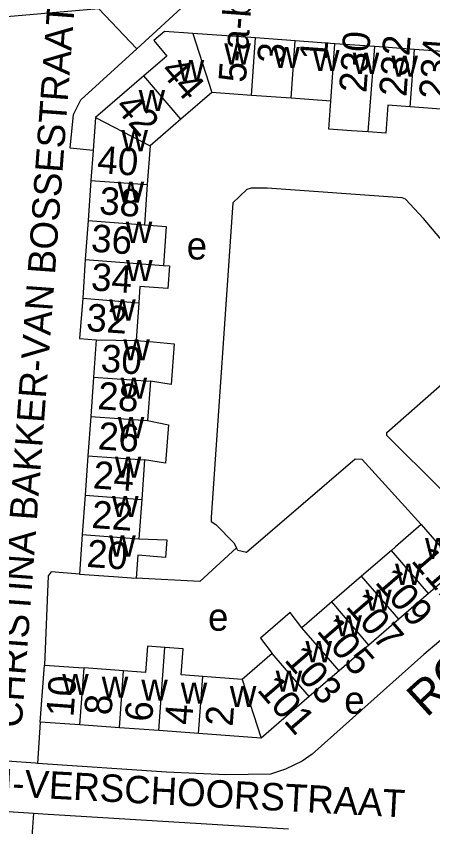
# Model space of a CAD drawing. Extents: x 159902 to 161769, y 383692 to 384875.
# Drawn here: x 160524 to 160584.8, y 384027.3 to 384145.4 of the extents above; entities that cross this region are included whole.
import ezdxf

# ---------------------------------------------------------------- set-up
doc = ezdxf.new("R2010")
doc.units = 0
for name, color, linetype in [('BLT_Basislijn', 7, 'Continuous'), ('BLT_Bebouwing', 7, 'Continuous'), ('BLT_Centroide', 7, 'Continuous'), ('BLT_Huisnummer', 7, 'Continuous'), ('BLT_Huisnummer_ tussenligend', 7, 'Continuous'), ('BLT_Huisnummer_reeks', 7, 'Continuous'), ('BLT_Onderverdeling_panden', 7, 'Continuous'), ('BLT_Straatnaam', 7, 'Continuous'), ('BLT_Straatnaam_verkleind', 7, 'Continuous')]:
    doc.layers.add(name, color=color, linetype=linetype)

msp = doc.modelspace()

# ---------------------------------------------------------------- linework, layer by layer
at = {"layer": 'BLT_Basislijn'}
for p, q in [((160527.54, 384042.53), (160527.14, 384036.5)), ((160526.52, 384029.24), (160526.04, 384022.51))]:
    msp.add_line(p, q, dxfattribs=at)
for points in [[(160541.6, 384140.66), (160549.25, 384147.65), (160552.82, 384148.62), (160554.65, 384148.85)], [(160509.95, 384136.94), (160519.25, 384145.08), (160536.04, 384146.55), (160541.6, 384140.66)], [(160535.25, 384125.85), (160531.91, 384126.2), (160532.4, 384131.11), (160533.47, 384133.24), (160541.6, 384140.66)], [(160585.91, 384076.54), (160578.09, 384084.32), (160578.09, 384084.74), (160597.85, 384102.11), (160597.75, 384111.32), (160594.69, 384114.92), (160593.48, 384115.14), (160588.64, 384111.22), (160587.65, 384110.93), (160583.44, 384115.94), (160580.8, 384118.74), (160580.32, 384118.93), (160560.65, 384120.34), (160558.3, 384120.35), (160557.69, 384120.18), (160555.62, 384118.2), (160552.47, 384072.33), (160552.47, 384071.77), (160553.15, 384071.33), (160555.77, 384068.67), (160556.14, 384067.93)], [(160583.12, 384071.32), (160574.47, 384080.78), (160573.47, 384080.87), (160557.63, 384067.24), (160556.34, 384067.55), (160556.14, 384067.93)], [(160556.14, 384067.93), (160550.83, 384063.04), (160541.51, 384063.49)], [(160533.23, 384064.1), (160529.1, 384064.45), (160528.69, 384063.85), (160528.15, 384050.84)], [(160592.64, 384060.12), (160592.26, 384059.78), (160583.51, 384052.39), (160567.19, 384037.86), (160565.76, 384036.84), (160563.32, 384035.66), (160561.13, 384034.92), (160554.58, 384034.83), (160545.94, 384035.22), (160527.14, 384036.5)], [(160527.14, 384036.5), (160526.83, 384036.52), (160518.54, 384037.11)], [(160517.93, 384029.81), (160518.36, 384029.79), (160526.52, 384029.24)], [(160526.52, 384029.24), (160527.92, 384029.15), (160563.74, 384026.98)]]:
    msp.add_lwpolyline(points, dxfattribs=at)
at = {"layer": 'BLT_Bebouwing'}
for p, q in [((160558.94, 384142.26), (160549.81, 384142.92)), ((160564.74, 384141.84), (160558.94, 384142.26)), ((160570.53, 384141.42), (160564.74, 384141.84)), ((160576.32, 384141), (160570.53, 384141.42)), ((160582.11, 384140.58), (160576.32, 384141)), ((160591.23, 384139.92), (160582.11, 384140.58)), ((160542.62, 384136.72), (160535.6, 384130.65)), ((160552.55, 384134.3), (160548.05, 384130.42)), ((160558.34, 384133.88), (160552.55, 384134.3)), ((160564.13, 384133.46), (160558.34, 384133.88)), ((160569.92, 384133.04), (160564.13, 384133.46)), ((160587.29, 384131.78), (160581.51, 384132.2)), ((160535.6, 384130.65), (160535.25, 384125.85)), ((160548.05, 384130.42), (160543.56, 384126.55)), ((160543.56, 384126.55), (160543.15, 384120.87)), ((160535.25, 384125.85), (160534.93, 384121.46)), ((160534.93, 384121.46), (160534.51, 384115.64)), ((160543.15, 384120.87), (160542.73, 384114.99)), ((160534.51, 384115.64), (160534.1, 384109.98)), ((160534.1, 384109.98), (160533.74, 384104.3)), ((160541.9, 384103.66), (160541.5, 384098.15)), ((160535.71, 384098.25), (160535.32, 384092.83)), ((160541.5, 384098.15), (160544.01, 384097.97)), ((160535.32, 384092.83), (160534.9, 384087.08)), ((160543.6, 384092.23), (160543.18, 384086.48)), ((160534.9, 384087.08), (160534.48, 384081.34)), ((160534.48, 384081.34), (160534.07, 384075.59)), ((160542.76, 384080.74), (160542.35, 384074.99)), ((160534.07, 384075.59), (160533.65, 384069.85)), ((160542.35, 384074.99), (160541.93, 384069.24)), ((160583.12, 384071.32), (160588.54, 384065.04)), ((160533.65, 384069.85), (160533.23, 384064.1)), ((160578.77, 384067.56), (160574.41, 384063.8)), ((160588.54, 384065.04), (160584.18, 384061.28)), ((160574.41, 384063.8), (160570.06, 384060.03)), ((160584.18, 384061.28), (160579.83, 384057.52)), ((160570.06, 384060.03), (160565.7, 384056.27)), ((160579.83, 384057.52), (160575.48, 384053.76)), ((160575.48, 384053.76), (160571.12, 384050)), ((160561.35, 384052.51), (160556.99, 384048.75)), ((160527.54, 384042.53), (160528.15, 384050.84)), ((160539.68, 384050.01), (160533.92, 384050.42)), ((160571.12, 384050), (160566.77, 384046.24)), ((160556.99, 384048.75), (160551.23, 384049.17)), ((160566.77, 384046.24), (160559.77, 384040.2)), ((160533.31, 384042.11), (160527.54, 384042.53)), ((160539.08, 384041.7), (160533.31, 384042.11)), ((160544.85, 384041.28), (160539.08, 384041.7)), ((160550.62, 384040.86), (160544.85, 384041.28)), ((160559.77, 384040.2), (160550.62, 384040.86))]:
    msp.add_line(p, q, dxfattribs=at)
for points in [[(160549.81, 384142.92), (160545.64, 384143.2), (160544.09, 384141.89), (160546, 384139.61), (160542.62, 384136.72)], [(160575.37, 384128.56), (160572.93, 384128.73), (160569.64, 384128.95), (160569.92, 384133.04)], [(160581.51, 384132.2), (160578.23, 384132.44), (160577.94, 384128.37), (160575.37, 384128.56)], [(160542.73, 384114.99), (160545.91, 384114.76), (160545.5, 384109.1)], [(160545.5, 384109.1), (160546.39, 384109.03), (160546.15, 384105.72), (160542.07, 384106.02), (160541.9, 384103.66)], [(160533.74, 384104.3), (160533.26, 384098.43), (160535.71, 384098.25)], [(160544.01, 384097.97), (160547.08, 384097.66), (160546.65, 384091.74), (160543.6, 384092.23)], [(160543.18, 384086.48), (160546.22, 384085.88), (160545.81, 384080.25), (160542.76, 384080.74)], [(160583.12, 384071.32), (160579.34, 384068.05), (160578.77, 384067.56)], [(160541.93, 384069.24), (160545.98, 384069.1), (160545.8, 384066.54), (160541.76, 384066.84), (160541.51, 384063.49)], [(160533.23, 384064.1), (160538.22, 384063.73), (160541.51, 384063.49)], [(160565.7, 384056.27), (160564.01, 384058.52), (160559.66, 384054.76), (160561.35, 384052.51)], [(160545.7, 384053.41), (160543.16, 384053.6), (160542.88, 384049.77), (160539.68, 384050.01)], [(160551.23, 384049.17), (160548.11, 384049.4), (160548.38, 384053.22), (160545.7, 384053.41)], [(160528.15, 384050.84), (160533.13, 384050.48), (160533.92, 384050.42)]]:
    msp.add_lwpolyline(points, dxfattribs=at)
at = {"layer": 'BLT_Onderverdeling_panden'}
for p, q in [((160549.81, 384142.92), (160552.55, 384134.3)), ((160558.34, 384133.88), (160558.94, 384142.26)), ((160564.13, 384133.46), (160564.74, 384141.84)), ((160569.92, 384133.04), (160570.53, 384141.42)), ((160575.37, 384128.56), (160576.32, 384141)), ((160581.51, 384132.2), (160582.11, 384140.58)), ((160548.05, 384130.42), (160542.62, 384136.72)), ((160535.6, 384130.65), (160543.56, 384126.55)), ((160534.93, 384121.46), (160543.15, 384120.87)), ((160534.51, 384115.64), (160542.73, 384114.99)), ((160534.1, 384109.98), (160545.5, 384109.1)), ((160533.74, 384104.3), (160541.9, 384103.66)), ((160535.71, 384098.25), (160541.5, 384098.15)), ((160535.32, 384092.83), (160543.6, 384092.23)), ((160534.9, 384087.08), (160543.18, 384086.48)), ((160534.48, 384081.34), (160542.76, 384080.74)), ((160534.07, 384075.59), (160542.35, 384074.99)), ((160533.65, 384069.85), (160541.93, 384069.24)), ((160584.18, 384061.28), (160578.77, 384067.56)), ((160579.83, 384057.52), (160574.41, 384063.8)), ((160575.48, 384053.76), (160570.06, 384060.03)), ((160571.12, 384050), (160565.7, 384056.27)), ((160544.85, 384041.28), (160545.7, 384053.41)), ((160566.77, 384046.24), (160561.35, 384052.51)), ((160533.31, 384042.11), (160533.92, 384050.42)), ((160539.08, 384041.7), (160539.68, 384050.01)), ((160550.62, 384040.86), (160551.23, 384049.17)), ((160556.99, 384048.75), (160559.77, 384040.2))]:
    msp.add_line(p, q, dxfattribs=at)

# ---------------------------------------------------------------- texts
at = {"layer": 'BLT_Centroide'}
for s, p in [('w', (160554.38, 384138.38)), ('w', (160561.53, 384137.86)), ('w', (160567.33, 384137.44)), ('w', (160573.12, 384137.02)), ('w', (160578.77, 384136.61)), ('w', (160547.58, 384135.98)), ('w', (160541.88, 384131.62)), ('w', (160539.37, 384125.75)), ('w', (160538.82, 384118.22)), ('w', (160540, 384112.38)), ('e', (160548.9, 384109.96)), ('w', (160540.05, 384106.81)), ('w', (160537.59, 384101.06)), ('w', (160539.65, 384095.25)), ('w', (160539.25, 384089.66)), ('w', (160538.84, 384083.91)), ('w', (160538.41, 384078.16)), ('w', (160538, 384072.41)), ('w', (160537.59, 384066.66)), ('w', (160583.66, 384066.3)), ('w', (160579.3, 384062.53)), ('w', (160574.94, 384058.78)), ('e', (160552.01, 384055.84)), ('w', (160570.59, 384055.02)), ('w', (160566.23, 384051.25)), ('w', (160561.88, 384046.97)), ('w', (160530.73, 384046.48)), ('w', (160536.5, 384046.06)), ('w', (160542.27, 384045.64)), ('w', (160548.03, 384045.22)), ('w', (160555.19, 384044.7)), ('e', (160571.88, 384043.74))]:
    msp.add_text(s, height=4, dxfattribs=at).set_placement(p)
at = {"layer": 'BLT_Huisnummer'}
for s, rotation, p in [('230', 85.8541, (160575.1, 384134.18)), ('234', 85.8541, (160586.75, 384133.22)), ('1', 85.8546, (160569.34, 384138.9)), ('44', 310.8099, (160544.89, 384137.35)), ('40', 355.854, (160535.75, 384122.58)), ('36', 355.8545, (160534.85, 384111.12)), ('32', 355.8475, (160534.15, 384099.56)), ('28', 355.849, (160535.81, 384088.16)), ('24', 355.849, (160535.15, 384076.61)), ('20', 355.8483, (160534.21, 384065.16)), ('111', 310.8165, (160581.52, 384065.98)), ('105', 310.812, (160567.73, 384055.74)), ('10', 85.8566, (160532.37, 384043.2)), ('101', 310.812, (160559.04, 384047.16)), ('6', 85.8497, (160543.84, 384042.49)), ('2', 85.8497, (160555.59, 384041.81))]:
    msp.add_text(s, height=4, rotation=rotation, dxfattribs=at).set_placement(p)
at = {"layer": 'BLT_Huisnummer_ tussenligend'}
for s, rotation, p in [('232', 85.8541, (160580.94, 384133.62)), ('3', 85.8546, (160563.15, 384138.45)), ('42', 310.8099, (160538.27, 384132.12)), ('38', 355.8545, (160536.04, 384116.58)), ('34', 355.8475, (160534.85, 384105.48)), ('30', 355.849, (160536.27, 384093.61)), ('26', 355.849, (160535.86, 384082.3)), ('22', 355.8483, (160534.93, 384070.84)), ('109', 310.812, (160576.25, 384062.85)), ('107', 310.812, (160571.98, 384059.3)), ('103', 310.812, (160563.01, 384051.53)), ('8', 85.8497, (160537.91, 384043.45)), ('4', 85.8497, (160549.67, 384042.04))]:
    msp.add_text(s, height=4, rotation=rotation, dxfattribs=at).set_placement(p)
at = {"layer": 'BLT_Huisnummer_reeks'}
msp.add_text('5-a-b', height=4, rotation=85.8546, dxfattribs=at).set_placement((160557.51, 384135.67))
at = {"layer": 'BLT_Straatnaam'}
msp.add_text('ROOSJE VOSSTRAAT', height=5, rotation=42.3212, dxfattribs=at).set_placement((160583.89, 384043.09))
at = {"layer": 'BLT_Straatnaam_verkleind'}
for s, rotation, p in [('CHRISTINA BAKKER-VAN BOSSESTRAAT', 85.7906, (160524.8, 384041.61)), ('ANNIE ROMEIN-VERSCHOORSTRAAT', 356.9549, (160484.19, 384033.75))]:
    msp.add_text(s, height=4, rotation=rotation, dxfattribs=at).set_placement(p)

doc.saveas('drawing.dxf')
